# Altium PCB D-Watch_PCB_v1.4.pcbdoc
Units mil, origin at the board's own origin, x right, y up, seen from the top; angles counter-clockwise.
Board outline 2086.61 x 1990.87 mil, 4 copper layers (Top Layer, Inner1, Inner2, Bottom Layer); 71 components, 58 nets, 274 pads, 111 vias.
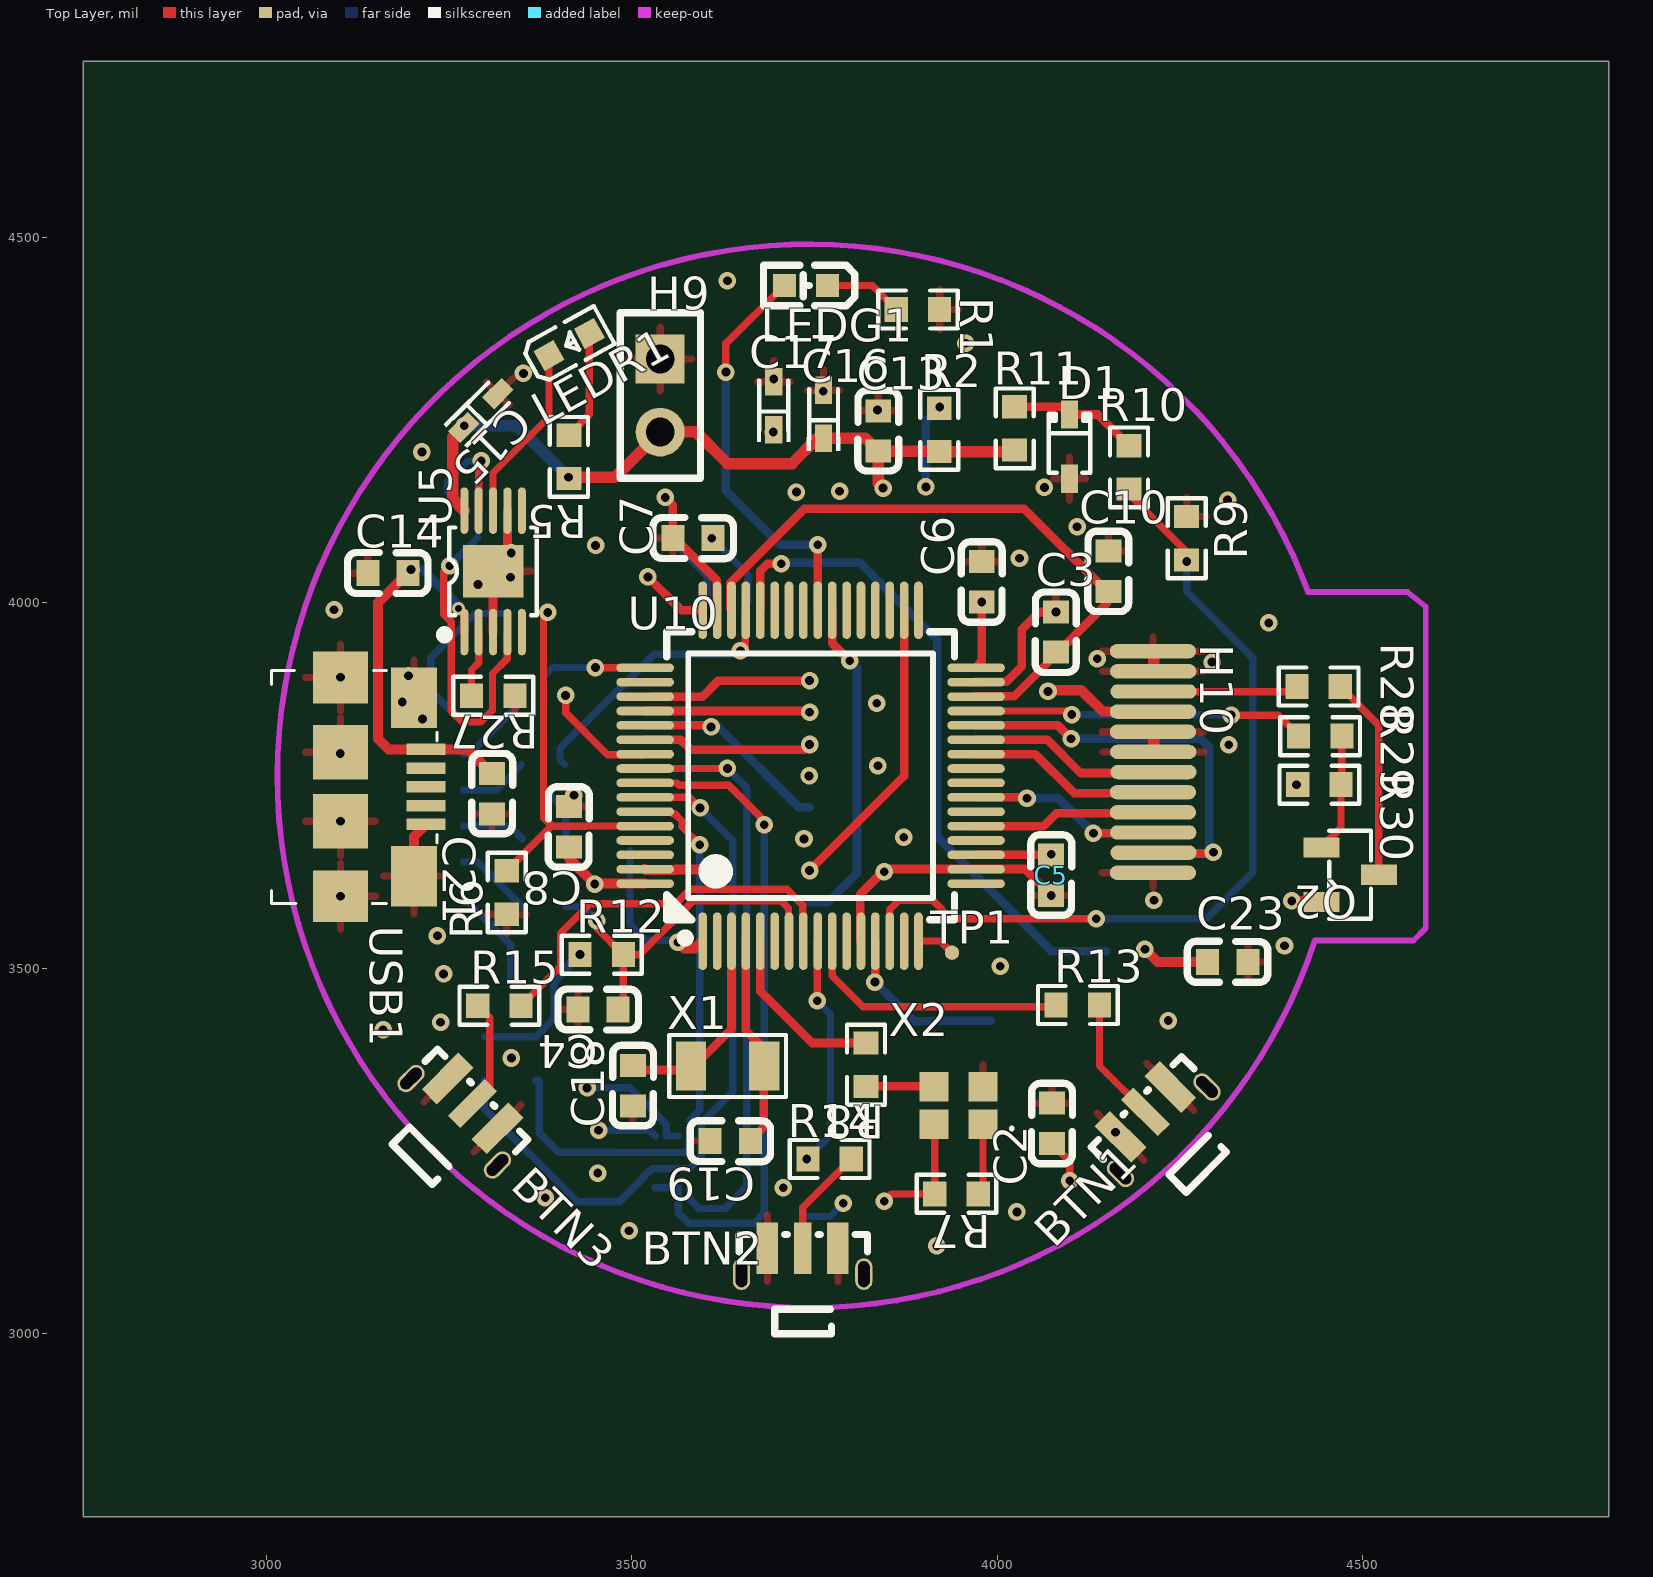
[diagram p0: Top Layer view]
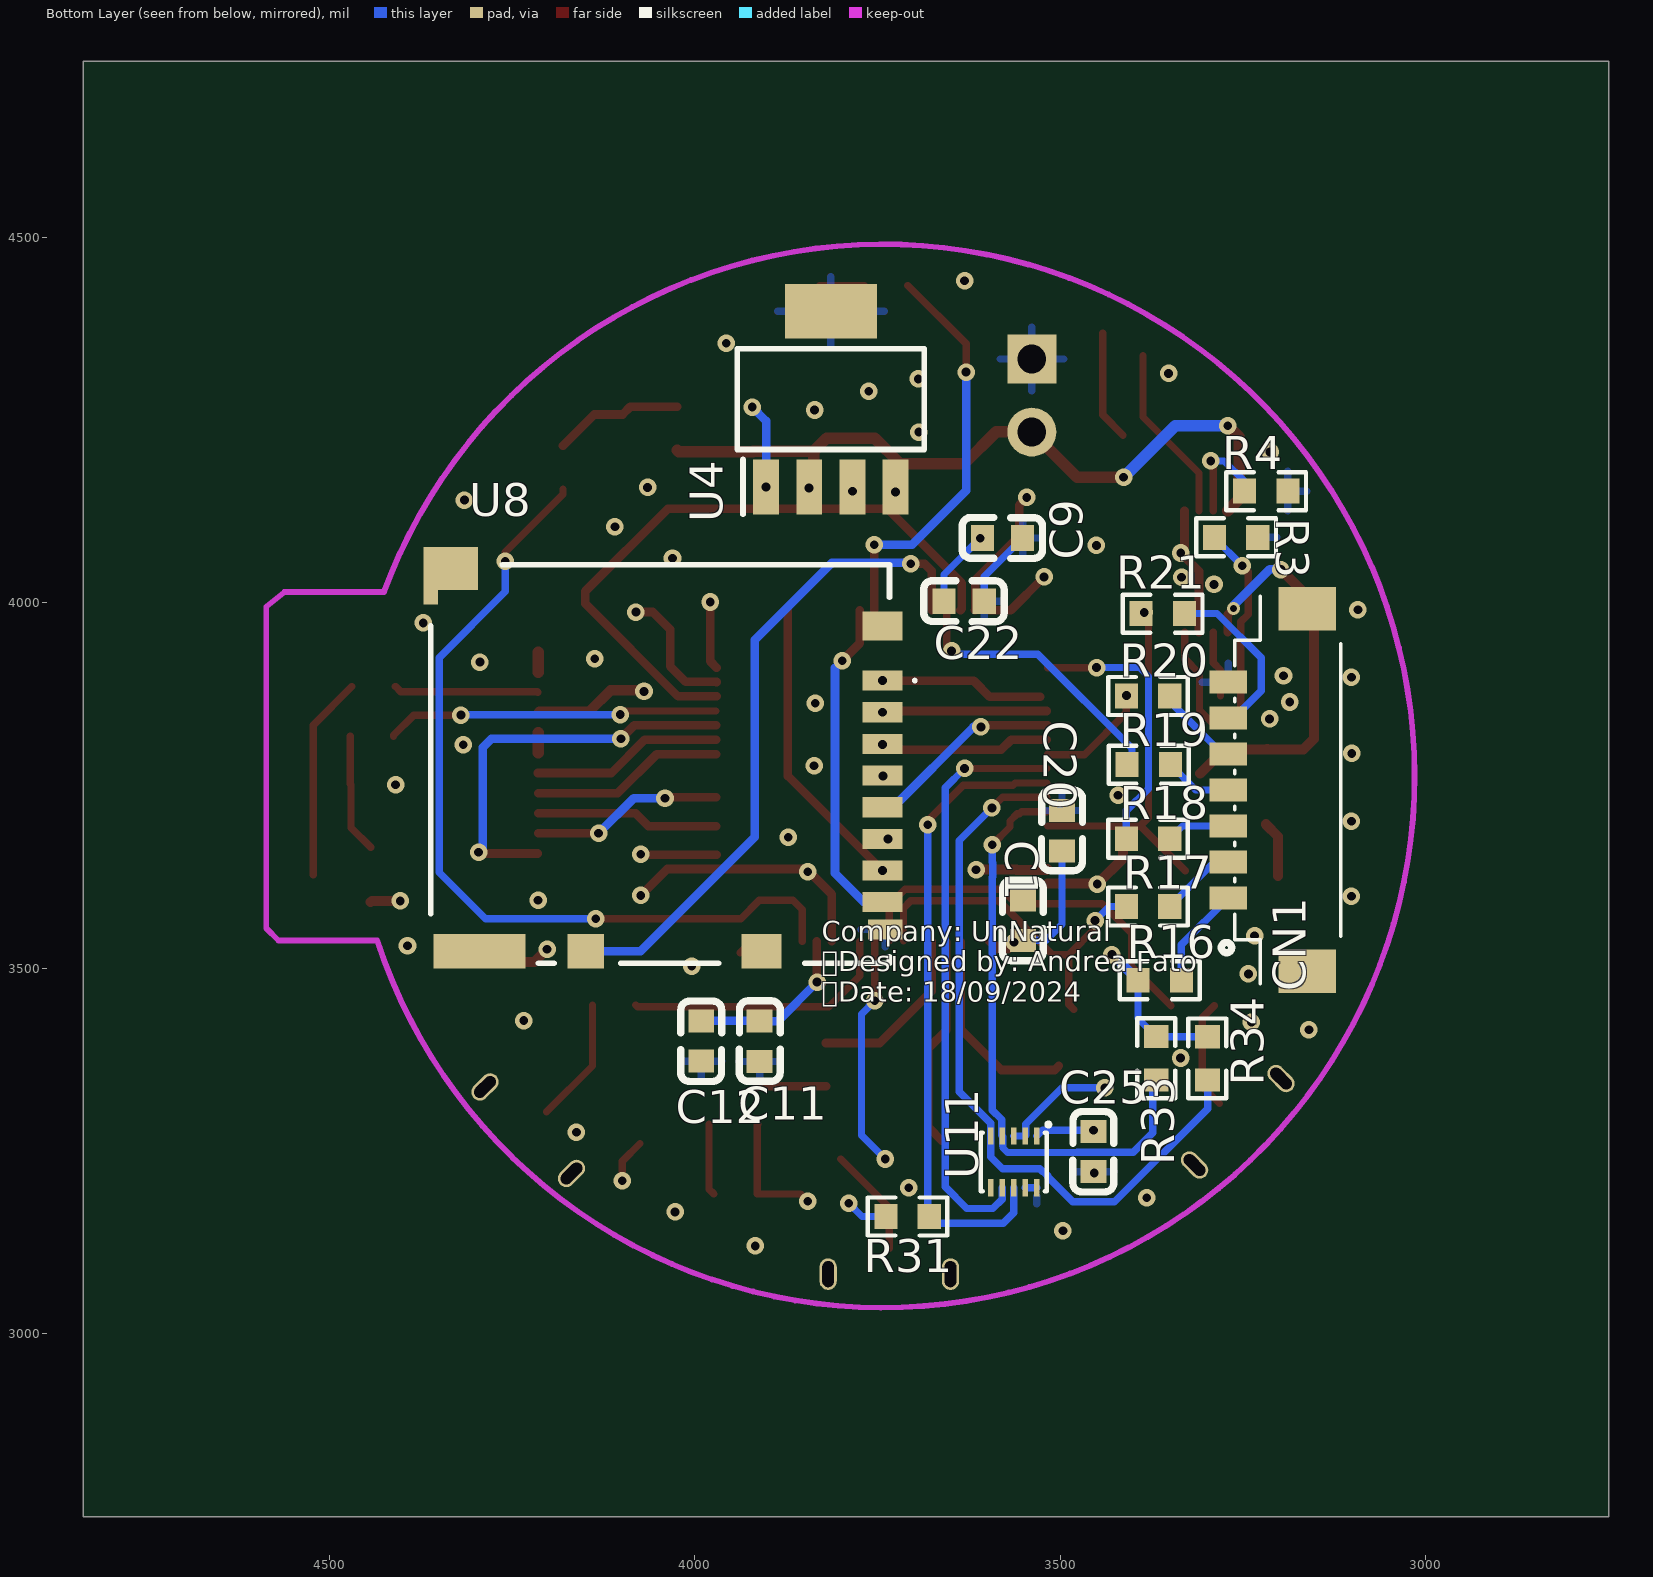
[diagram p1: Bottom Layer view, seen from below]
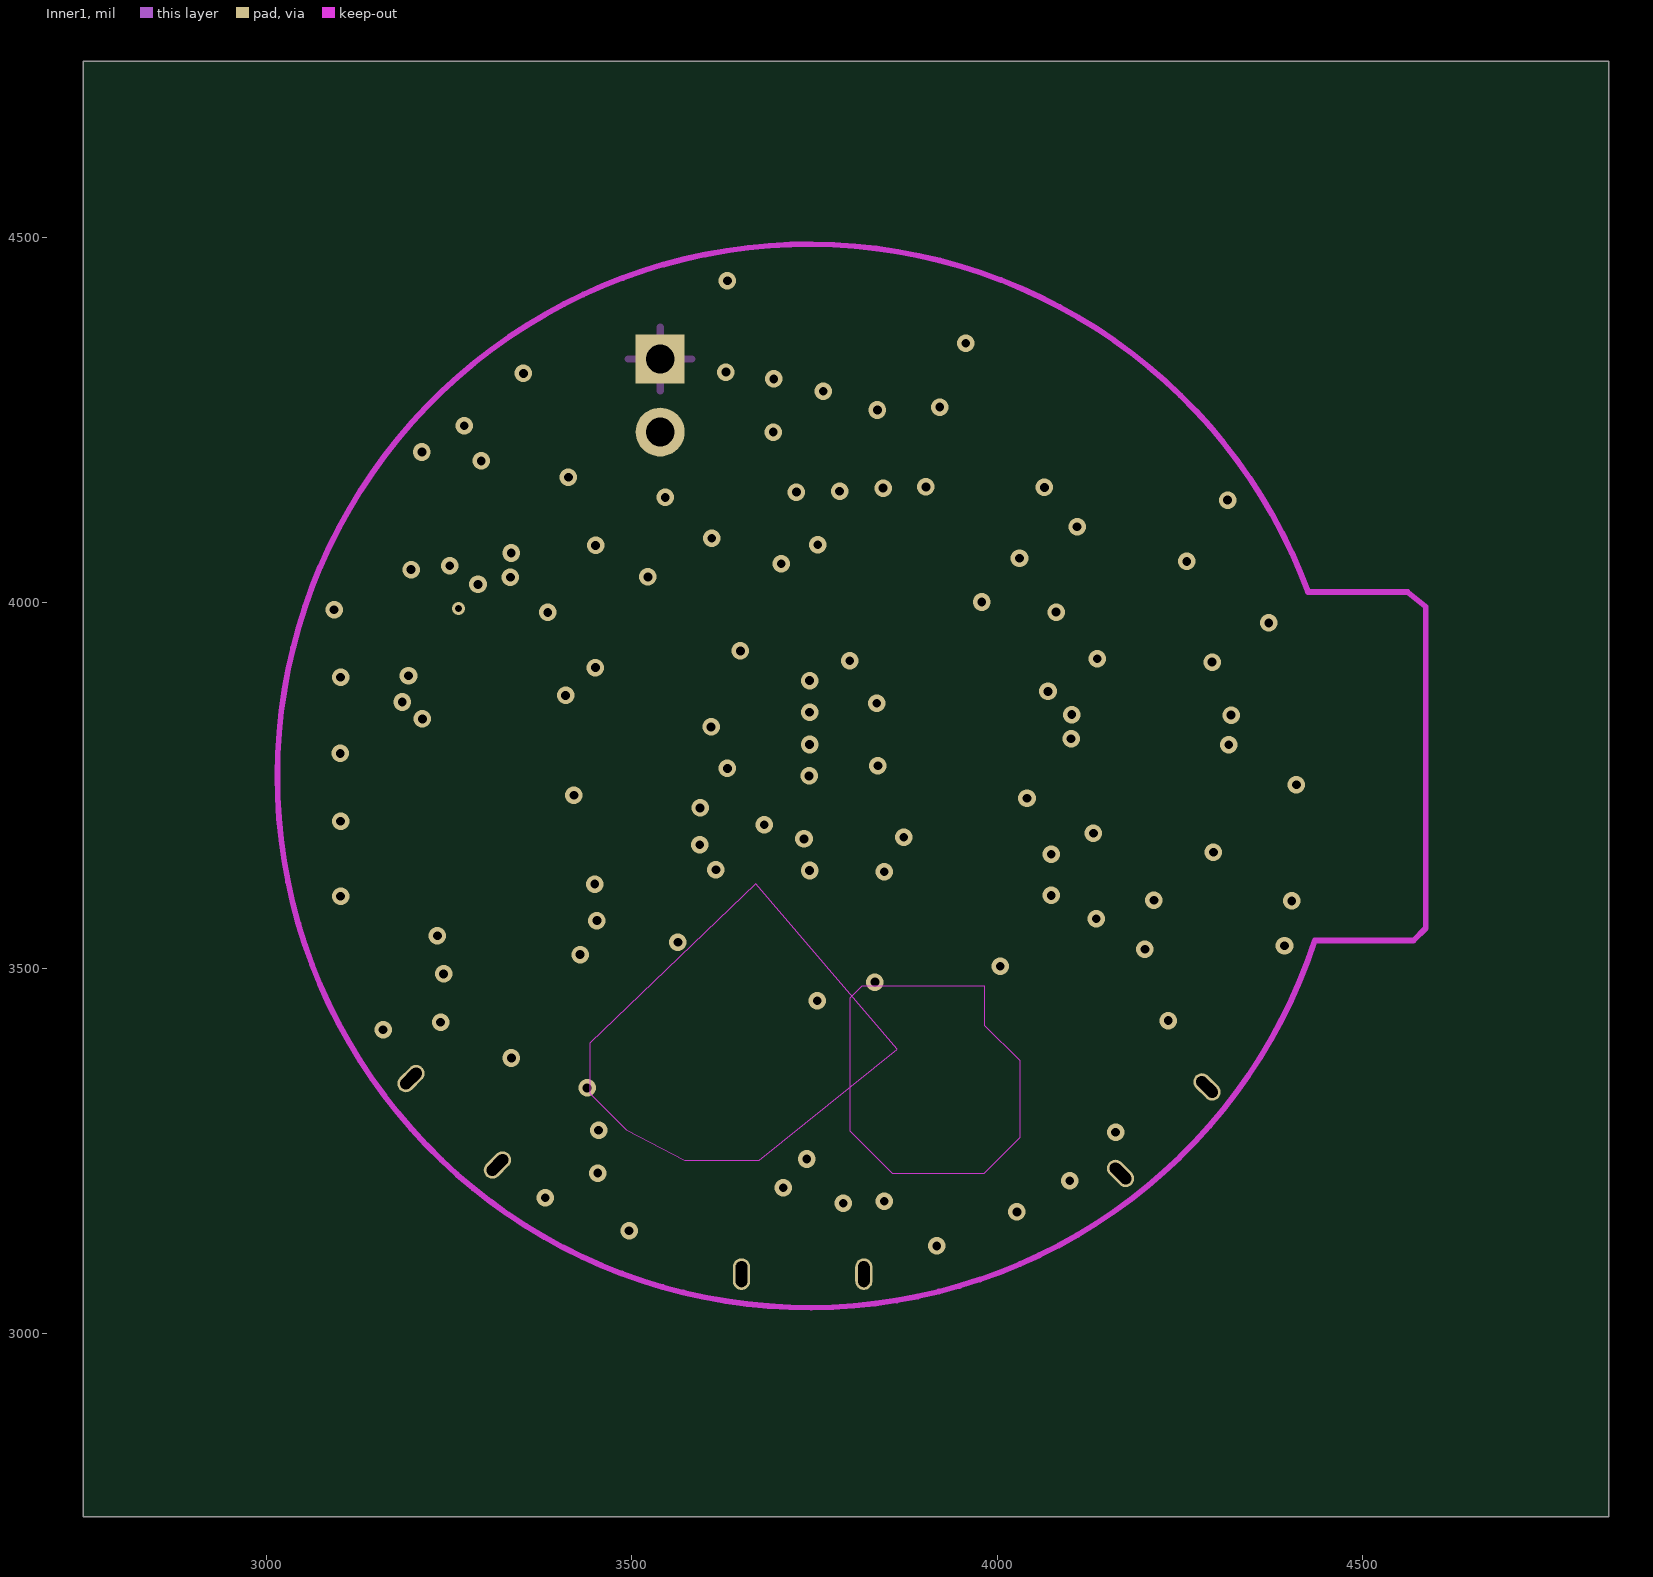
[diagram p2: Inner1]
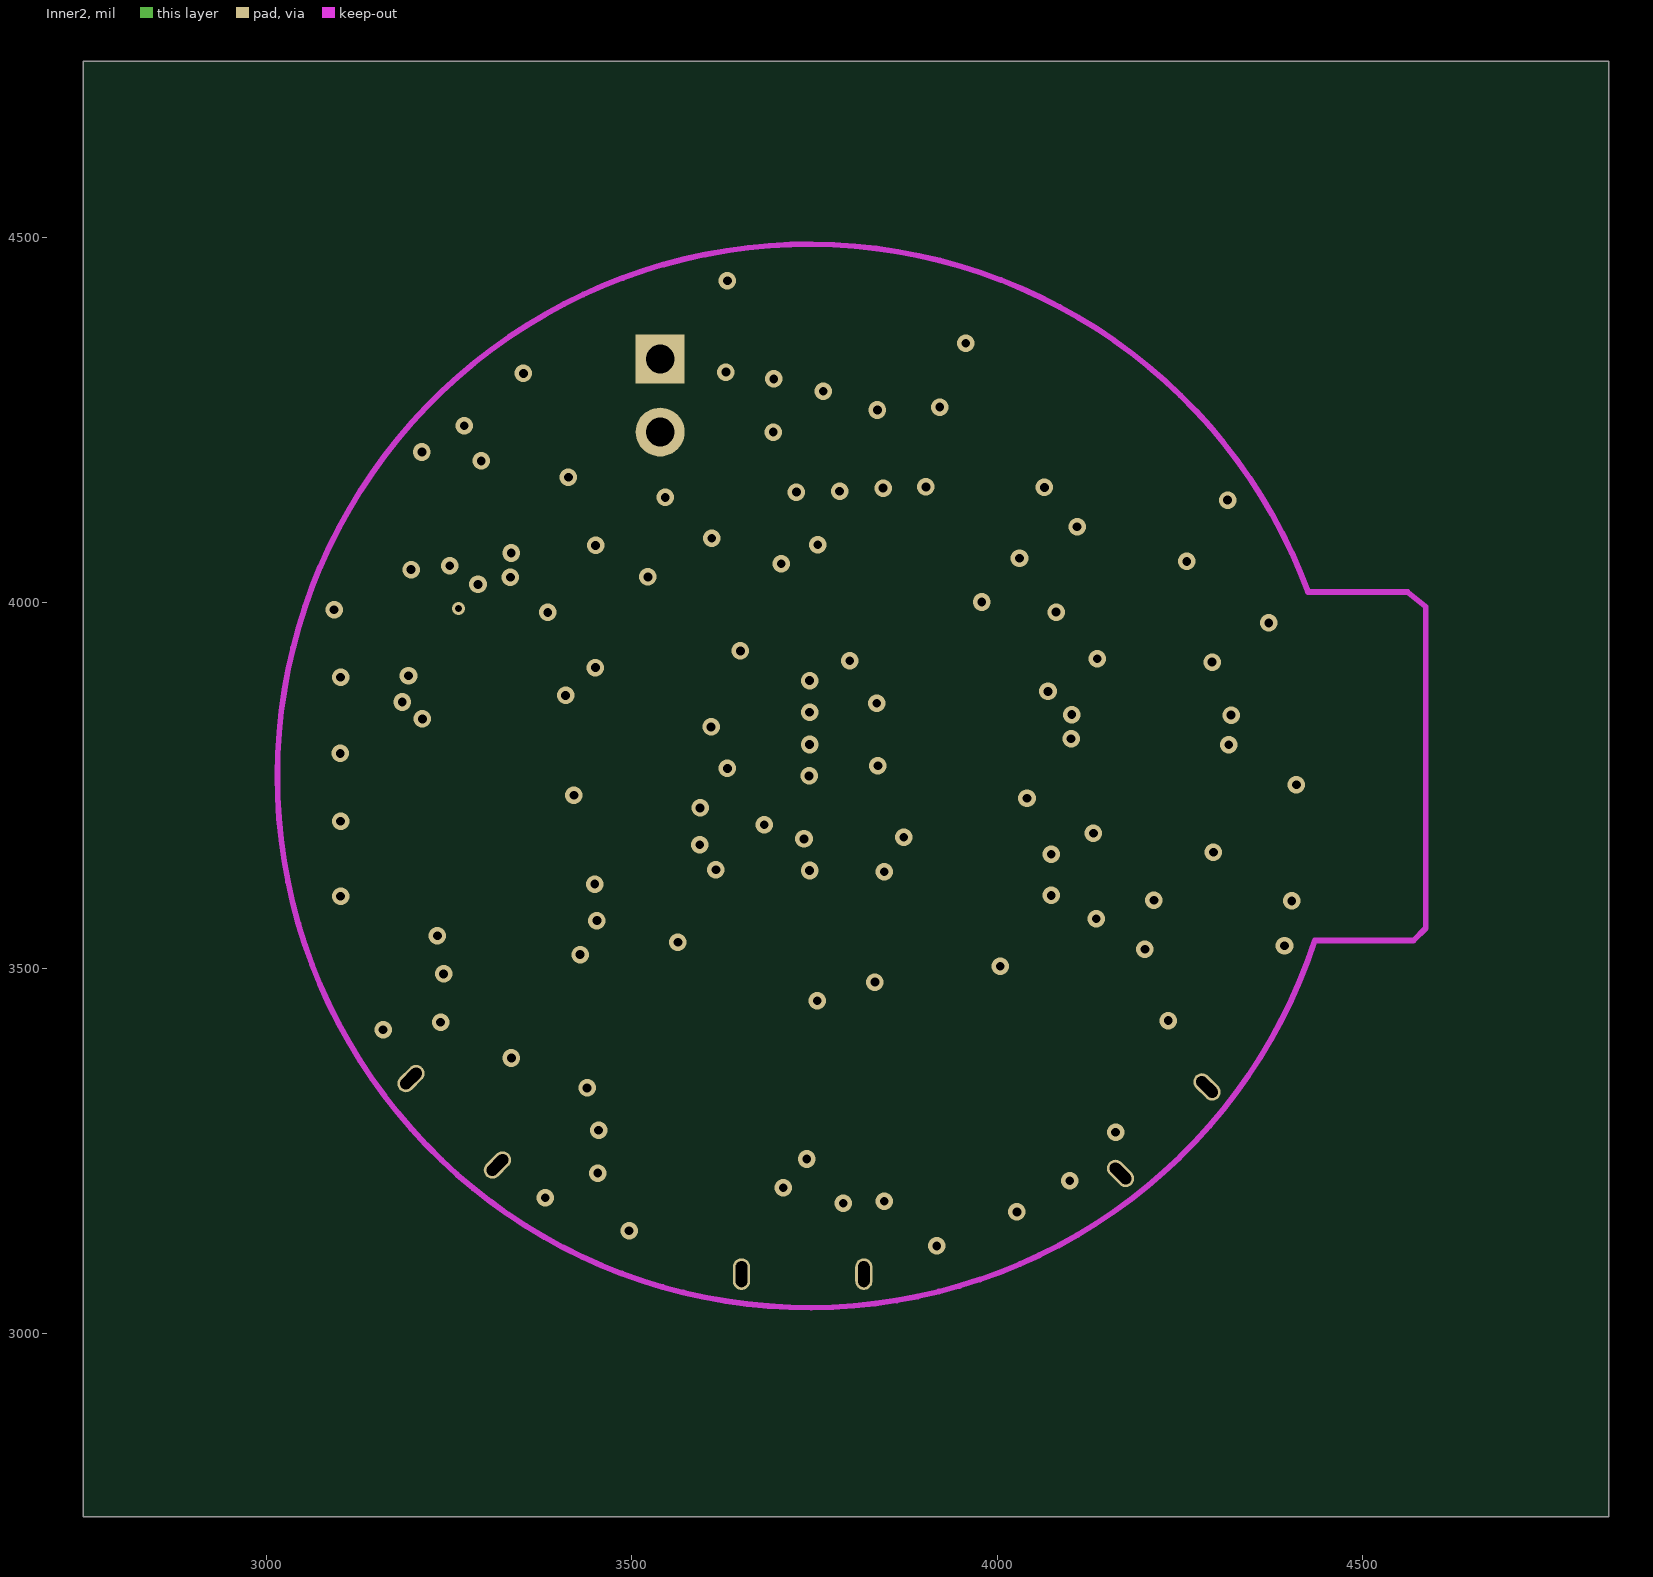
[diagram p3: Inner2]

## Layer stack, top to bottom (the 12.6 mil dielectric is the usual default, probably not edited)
Top Layer: signal copper (thickness not stored)
Dielectric: dielectric 12.6, FR-4, Dk 4.8
Inner1: signal copper (thickness not stored)
Dielectric: dielectric 12.6, FR-4, Dk 4.8
Inner2: signal copper (thickness not stored)
Dielectric: dielectric 12.6, FR-4, Dk 4.8
Bottom Layer: signal copper (thickness not stored)

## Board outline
4836.61,2750 2750,2750 2750,4740.87 4836.61,4740.87

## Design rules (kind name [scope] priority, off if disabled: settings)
Clearance copperThickness1oz [All] p1: gap=7 ignorepadtopadclearanceinfootprint=FALSE except(0.4: SMDPad-SMDPad; 4: Track-Track; 6: Track-SMDPad Track-THPad SMDPad-THPad THPad-THPad Track-Via SMDPad-Via THPad-Via Via-Via Track-Fill SMDPad-Fill THPad-Fill Via-Fill Fill-Fill SMDPad-Region THPad-Region Via-Region Fill-Region Region-Region Track-Poly SMDPad-Poly THPad-Poly Via-Poly Fill-Poly Poly-Poly Track-Text SMDPad-Text THPad-Text Via-Text Fill-Text Region-Text Poly-Text Text-Text; 6.9: Track-Hole SMDPad-Hole THPad-Hole Via-Hole Fill-Hole Region-Hole Poly-Hole Text-Hole Sheet-Hole; 11.8: Track-Region Region-Poly Track-Sheet SMDPad-Sheet THPad-Sheet Via-Sheet Fill-Sheet Region-Sheet Poly-Sheet Text-Sheet)
Clearance copperThickness2oz [All] p1: gap=7 ignorepadtopadclearanceinfootprint=FALSE except(6: Track-SMDPad SMDPad-SMDPad Track-THPad SMDPad-THPad THPad-THPad Track-Via SMDPad-Via THPad-Via Via-Via SMDPad-Fill THPad-Fill Via-Fill Fill-Fill Track-Region SMDPad-Region THPad-Region Via-Region Region-Region Track-Poly SMDPad-Poly THPad-Poly Via-Poly Fill-Poly Region-Poly Poly-Poly Track-Text SMDPad-Text THPad-Text Via-Text Fill-Text Region-Text Poly-Text Text-Text; 6.9: Track-Hole SMDPad-Hole THPad-Hole Via-Hole Fill-Hole Region-Hole Poly-Hole Text-Hole Sheet-Hole; 8: Track-Track; 11.8: Track-Fill Fill-Region Track-Sheet SMDPad-Sheet THPad-Sheet Via-Sheet Fill-Sheet Region-Sheet Poly-Sheet Text-Sheet)
Clearance BGA [All] p1: gap=7 ignorepadtopadclearanceinfootprint=FALSE except(3.9: Track-Track Track-SMDPad SMDPad-SMDPad Track-THPad SMDPad-THPad THPad-THPad Track-Via SMDPad-Via THPad-Via Via-Via Track-Fill SMDPad-Fill THPad-Fill Via-Fill Fill-Fill Track-Region SMDPad-Region THPad-Region Via-Region Fill-Region Region-Region Track-Poly SMDPad-Poly THPad-Poly Via-Poly Fill-Poly Region-Poly Poly-Poly Track-Hole SMDPad-Hole THPad-Hole Via-Hole Fill-Hole Region-Hole Poly-Hole Text-Hole Sheet-Hole; 6: Track-Text SMDPad-Text THPad-Text Via-Text Fill-Text Region-Text Poly-Text Text-Text; 11.8: Track-Sheet SMDPad-Sheet THPad-Sheet Via-Sheet Fill-Sheet Region-Sheet Poly-Sheet Text-Sheet)
DiffPairsRouting differentialPair [All] p1: maxuncoupledlength=10 maxlimit=5.9843 mostfreqgap=5.9843 toplayer_minwidth=5 toplayer_prefwidth=10 toplayer_maxwidth=100 bottomlayer_minwidth=5 bottomlayer_prefwidth=10 bottomlayer_maxwidth=100 midlayer1_minwidth=5 midlayer1_prefwidth=10 midlayer1_maxwidth=100 midlayer2_minwidth=5 midlayer2_prefwidth=10 midlayer2_maxwidth=100
PasteMaskExpansion pasteMaskExpansion [All] p1:
PlaneConnect innerPlane [All] p1: planeconnectstyle=Relief reliefexpansion=20 reliefentries=4 reliefconductorwidth=10 reliefairgap=10
PolygonConnect copperRegion [All] p1: connectstyle=Relief reliefentries=4 reliefconductorwidth=10 polygonreliefangle="90 Angle" airgapwidth=10
PolygonConnect copperRegionOSC [All] p1: connectstyle=Relief reliefentries=4 reliefconductorwidth=10 polygonreliefangle="90 Angle" airgapwidth=10
RoutingVias viaSize [All] p1: viastyle="Through Hole" holewidth=12.0078 minholewidth=5.9056 maxholewidth=248.0314 width=24.0158 minwidth=9.8426 maxwidth=393.7008
SolderMaskExpansion solderMaskExpansion [All] p1: useseparateexpansions=TRUE expansion=2.0079 expansionbottom=2.0079
Width copperThickness1oz [All] p1: maxlimit=100 minlimit=4 preferedwidth=10
Width copperThickness2oz [All] p1: maxlimit=100 minlimit=8 preferedwidth=10

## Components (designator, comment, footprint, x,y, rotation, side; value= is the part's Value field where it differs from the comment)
BTN1 "436333033816" SW-SMD_436333033816 4232.96,3273.74 r45 top
BTN2 "436333033816" SW-SMD_436333033816 3734.06,3074.8 r0 top
BTN3 "436333033816" SW-SMD_436333033816 3252.36,3285.27 r315 top
C1 "GCJ188R71C104KA01D" C0603 3551.18,3565.98 r90 bottom
C2 "GCJ188R71C104KA01D" C0603 4075.2,3288.03 r90 top
C3 "GCJ188R71C104KA01D" C0603 4080.44,3960.24 r90 top
C4 "GCJ188R71C104KA01D" C0603 3454.06,3443.86 r180 top
C5 "GCJ188R71C104KA01D" C0603 4074.02,3627.4 r270 top
C6 "GCJ188R71C104KA01D" C0603 3979.06,4028.86 r90 top
C7 "GCJ188R71C104KA01D" C0603 3584.06,4088.86 r180 top
C8 "GCJ188R71C104KA01D" C0603 3414.06,3693.86 r90 top
C9 "GCJ188C70J475KE02D" C0603 3579.06,4088.86 r180 bottom
C10 "GCJ188R71C104KA01D" C0603 4152.36,4043.54 r90 top
C11 "GCJ188R71C104KA01D" C0603 3911.42,3400.23 r270 bottom
C12 "CC0603KRX7R5BB105" C0603 3991.34,3400.62 r90 bottom
C13 "CC0603KRX7R5BB105" C0603 3837.4,4235.27 r270 top
C14 "CC0603KRX7R5BB105" C0603 3166.54,4040.78 r0 top
C15 "T58MM106M6R3C0300" CAP-SMD_L1.6-W0.8-RD 3293.7,4263.22 r225 top
C16 "T58MM106M6R3C0300" CAP-SMD_L1.6-W0.8-RD 3762.6,4258.1 r270 top
C17 "T58MM106M6R3C0300" CAP-SMD_L1.6-W0.8-RD 3694.49,4269.91 r270 top
C18 "CAP_0603" C0603 3501.72,3339.33 r270 top
C19 "CAP_0603" C0603 3634.79,3263.71 r180 top
C20 "AC0603KRX7R6BB105" C0603 3497.76,3688.5 r270 bottom
C21 "GCJ188R71C104KA01D" C0603 3309.06,3738.81 r270 top
C22 "GCJ188R71C104KA01D" C0603 3631.7,4002.32 r180 bottom
C23 "GCJ188R71C104KA01D" C0603 4315.71,3508.82 r0 top
C25 "AC0603KRX7R6BB105" C0603 3454.73,3249.44 r90 bottom
CN1 "53398-0771" CONN-SMD_7P-P1.25_53398-0771 3216.35,3744.04 r90 bottom
D1 "TDZ3V6J,115" SOD-323_L1.7-W1.3-LS2.5-RD-1 4099.06,4213.86 r270 top
H9 "HDR-F_2.54_1x2P" HDR-TH_2P-P2.54-V-F 3539.06,4283.86 r270 top
H10 "HDR-M_2.54_1x12P" HDR-TH_12P-P2.54-V-M 4210.96,3781.34 r270 top
LEDG1 "APT1608MGC" LED-SMD_L1.6-W0.8-RD 3738.4,4434.41 r180 top
LEDR1 "APT1608SURCK" LED0603-RD 3414.57,4353.77 r28.78 top
Q2 "NSS40200LT1G" SOT-23-3_L2.9-W1.3-P1.90-LS2.4-BR 4483.07,3628.18 r180 top
R1 "Res_0603" R0603 3891.72,4401.47 r180 top
R2 "Res_0603" R0603 3920.87,4236.84 r90 top
R3 "Res_0603" R0603 3259.46,4089.72 r0 bottom
R4 "Res_0603" R0603 3218.39,4153.03 r180 bottom
R5 "Res_0603" R0603 3414.22,4199.93 r90 top
R6 "Res_0603" R0603 3329.06,3603.86 r90 top
R7 "Res_0603" R0603 3944.49,3191.44 r180 top
R8 "Res_0603" R0603 3820.74,3368.21 r90 top
R9 "Res_0603" R0603 4259.4,4088.52 r90 top
R10 "Res_0603" R0603 4180.58,4185.49 r90 top
R11 "Res_0603" R0603 4024.06,4238.86 r270 top
R12 "Res_0603" R0603 3459.06,3518.86 r0 top
R13 "Res_0603" R0603 4110.47,3449.96 r180 top
R14 "Res_0603" R0603 3770.87,3239.21 r180 top
R15 "Res_0603" R0603 3319.06,3448.86 r0 top
R16 "Res_0603" R0603 3364.06,3483.86 r180 bottom
R17 "Res_0603" R0603 3380,3584.67 r180 bottom
R18 "Res_0603" R0603 3380,3677.37 r180 bottom
R19 "Res_0603" R0603 3379.06,3778.86 r180 bottom
R20 "Res_0603" R0603 3380,3872.77 r180 bottom
R21 "Res_0603" R0603 3360,3985.47 r180 bottom
R27 "Res_0603" R0603 3310.63,3873.06 r180 top
R28 "Res_0603" R0603 4439.96,3885.64 r180 top
R29 "Res_0603" R0603 4442.12,3817.78 r180 top
R30 "Res_0603" R0603 4440.94,3751.41 r0 top
R31 "Res_0603" R0603 3709.06,3160.47 r0 bottom
R33 "Res_0603" R0603 3368.9,3377 r90 bottom
R34 "Res_0603" R0603 3298.86,3376.88 r90 bottom
TP1 "Test-Point" Test-Point-0.5mm 3938.33,3521.56 r0 top
U4 "LP3874EMP-3.3_NOPB_" SOT150P700X180-5N 3814.06,4278.86 r90 bottom
U5 "BQ24092DGQR" MSOP-10_L3.0-W3.0-P0.50-LS5.0-BL-EP 3310.39,4043.27 r0 top
U8 "DM3BT-DSF-PEJS_" DM3BTDSFPEJS 4043.65,3788.45 r270 bottom
U10 "STM32H7B0RBT6" LQFP-64_L10.0-W10.0-P0.50-LS12.0-BL 3744.88,3763.62 r0 top
U11 "FXLS8964AFR3" DFN-10_L2.0-W2.0-P0.40-BL 3563.78,3235.27 r0 bottom
USB1 "10118192-0001LF" MICRO-USB-SMD_10118192-0001LF_1 3160.31,3748.38 r270 top
X1 "NX3215SA-32.768K-STD-MUA-9" CRYSTAL-SMD_L3.2-W1.5-1 3631.32,3366.42 r0 top
X2 "EC5625ETTTS-25.000M_TR_" EC5625ETTTS25000MTR 3947.25,3312.44 r180 top

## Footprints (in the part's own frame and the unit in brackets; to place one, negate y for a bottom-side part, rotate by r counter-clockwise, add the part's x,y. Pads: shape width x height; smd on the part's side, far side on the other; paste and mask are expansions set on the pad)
C0603 [mm]
  rect 0.8x0.9 smd: 1(-0.7,0) 2(0.7,0)
  silkscreen extent -1.41,-0.71 1.39,0.72
CAP-SMD_L1.6-W0.8-RD [mil]
  rect 37.57x23.39 smd: 1(32.86,0) 2(-32.86,0)
  silkscreen extent -34,-23 49,23
CONN-SMD_7P-P1.25_53398-0771 [mm]
  rect 0.8x1.3 smd: 1(-3.75,1.375) 2(-2.5,1.375) 3(-1.25,1.375) 4(0,1.375) 5(1.25,1.375) 6(2.5,1.375) 7(3.75,1.375)
  rect 1.5x2 smd: 8(6.3,-1.375) 9(-6.3,-1.375)
  silkscreen extent -6.73,-2.54 6.73,1.61
CRYSTAL-SMD_L3.2-W1.5-1 [mm]
  rect 1.05x1.7 smd: 1(-1.275,0) 2(1.275,0)
  silkscreen extent -2.03,-1.08 2.03,1.08
DFN-10_L2.0-W2.0-P0.40-BL [mm]
  rect 0.2x0.6 smd: 1(-0.8,-0.9) 2(-0.4,-0.9) 3(0,-0.9) 4(0.4,-0.9) 5(0.8,-0.9) 6(0.8,0.9) 7(0.4,0.9) 8(0,0.9) 9(-0.4,0.9) 10(-0.8,0.9)
  silkscreen extent -1.26,-1.36 1.14,1.02
DM3BTDSFPEJS [mm]
  rect 0.7x1.4 smd: 1(-2.675,7.625) 2(-1.575,7.625) 3(-0.475,7.625) 4(0.625,7.625) 5(1.725,7.625) 6(2.825,7.625) 7(3.925,7.625) 8(5.025,7.625)
  rect 1.2x1.27 smd: 9(6.725,-2.68)
  rect 0.7x1.2 smd: 10(5.975,7.725)
  rect 1x1.4 smd: 11(-4.575,7.625)
  rect 1.2x1.397 smd: 12(6.725,3.425)
  rect 1.2x3.2 smd: 13(6.725,-6.375)
  rect 1.5x1.9 smd: 14(-6.575,-7.375)
  rect 0.5x0.5 smd: 15(-5.575,-8.075)
  silkscreen extent -6.7,-8.07 7.15,8.8
EC5625ETTTS25000MTR [mm]
  rect 1x1.016 smd: 1(-0.85,0.65) 2(-0.85,-0.65) 3(0.85,-0.65) 4(0.85,0.65)
  silkscreen extent -1.9,0.75 -1.8,0.85
HDR-TH_2P-P2.54-V-F [mm]
  rect 1.7x1.7 hole 1: 1(-1.27,0)
  round 1.7 hole 1: 2(1.27,0)
  silkscreen extent -2.88,-1.39 2.88,1.4
HDR-TH_12P-P2.54-V-M [mm]
  oval 0.5x3 smd: 1(-3.877,0.059) 2(-3.177,0.069) 3(-2.477,0.079) 4(-1.777,0.059) 5(-1.077,0.059) 6(-0.377,0.069) 7(0.323,0.079) 8(1.023,0.059) 9(1.723,0.059) 10(2.423,0.069) 11(3.123,0.079) 12(3.823,0.059)
LED0603-RD [mm]
  rect 0.8x0.8 smd: 1(-0.799,0) 2(0.799,0)
  silkscreen extent -1.49,-0.75 1.39,0.76
LED-SMD_L1.6-W0.8-RD [mm]
  rect 0.8x0.8 smd: 1(-0.75,0) 2(0.75,0)
  silkscreen extent -1.7,-0.7 1.47,0.7
LQFP-64_L10.0-W10.0-P0.50-LS12.0-BL [mm]
  oval 0.3x2 smd: 1(-3.75,-5.75) 2(-3.25,-5.75) 3(-2.75,-5.75) 4(-2.25,-5.75) 5(-1.75,-5.75) 6(-1.25,-5.75) 7(-0.75,-5.75) 8(-0.25,-5.75) 9(0.25,-5.75) 10(0.75,-5.75) 11(1.25,-5.75) 12(1.75,-5.75) 13(2.25,-5.75) 14(2.75,-5.75) 15(3.25,-5.75) 16(3.75,-5.75) 33(3.75,5.75) 34(3.25,5.75) 35(2.75,5.75) 36(2.25,5.75) 37(1.75,5.75) 38(1.25,5.75) 39(0.75,5.75) 40(0.25,5.75) 41(-0.25,5.75) 42(-0.75,5.75) 43(-1.25,5.75) 44(-1.75,5.75) 45(-2.25,5.75) 46(-2.75,5.75) 47(-3.25,5.75) 48(-3.75,5.75)
  oval 2x0.3 smd: 17(5.75,-3.75) 18(5.75,-3.25) 19(5.75,-2.75) 20(5.75,-2.25) 21(5.75,-1.75) 22(5.75,-1.25) 23(5.75,-0.75) 24(5.75,-0.25) 25(5.75,0.25) 26(5.75,0.75) 27(5.75,1.25) 28(5.75,1.75) 29(5.75,2.25) 30(5.75,2.75) 31(5.75,3.25) 32(5.75,3.75) 49(-5.75,3.75) 50(-5.75,3.25) 51(-5.75,2.75) 52(-5.75,2.25) 53(-5.75,1.75) 54(-5.75,1.25) 55(-5.75,0.75) 56(-5.75,0.25) 57(-5.75,-0.25) 58(-5.75,-0.75) 59(-5.75,-1.25) 60(-5.75,-1.75) 61(-5.75,-2.25) 62(-5.75,-2.75) 63(-5.75,-3.25) 64(-5.75,-3.75)
  silkscreen extent -5,-5.79 5,5
MICRO-USB-SMD_10118192-0001LF_1 [mm]
  rect 0.4x1.35 smd: 1(-1.3,1.487) 2(-0.65,1.487) 3(0,1.487) 4(0.65,1.487) 5(1.3,1.487)
  rect 1.8x1.9 smd: 6(-3.8,-1.487) 6(3.8,-1.487)
  rect 2.1x1.6 smd: 6(-3.1,1.063) 6(3.1,1.063)
  rect 1.9x1.9 smd: 6(-1.199,-1.487) 6(1.199,-1.487)
  silkscreen extent -4.05,-3.89 4.05,1.86
MSOP-10_L3.0-W3.0-P0.50-LS5.0-BL-EP [mm]
  oval 0.28x1.62 smd: 1(-1,-2.11) 2(-0.5,-2.11) 3(0,-2.11) 4(0.5,-2.11) 5(1,-2.11) 6(1,2.11) 7(0.5,2.11) 8(0,2.11) 9(-0.5,2.11) 10(-1,2.11)
  rect 2.1x1.83 smd: 11(0,0)
  silkscreen extent -1.84,-2.35 1.52,1.52
R0603 [mil]
  rect 31.75x34.02 smd: 1(-29.66,0) 2(29.66,0)
  silkscreen extent -55,-26 55,26
SOD-323_L1.7-W1.3-LS2.5-RD-1 [mm]
  rect 0.985x0.6 smd: 1(-1.118,0) 2(1.118,0)
  silkscreen extent -1.15,-0.73 0.9,0.73
SOT150P700X180-5N [mm]
  rect 1.9x0.9 smd: 1(-3.05,2.25) 2(-3.05,0.75) 3(-3.05,-0.75) 4(-3.05,-2.25)
  rect 1.9x3.2 smd: 5(3.05,0)
  silkscreen extent -4,-3.25 1.75,3.25
SOT-23-3_L2.9-W1.3-P1.90-LS2.4-BR [mm]
  rect 1.25x0.7 smd: 1(1,-0.95) 2(1,0.95) 3(-1,0)
  silkscreen extent -0.73,-1.53 0.73,1.53
SW-SMD_436333033816 [mm]
  rect 0.75x1.8 smd: 1(-1.225,1.075) 3(1.225,1.075)
  rect 0.6x1.8 smd: 2(0,1.075)
  oval 0.6x1.1 hole 0.4 slot 0.9 at 90 deg: 6(-2.125,0.175) 6(2.125,0.175)
  silkscreen extent -2.2,-1.9 2.25,1.55
Test-Point-0.5mm [mm]
  round 0.5 smd: 1(0,0)

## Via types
v1: diameter 24.02, hole 12.01, Top Layer to Bottom Layer, 110 vias
v2: diameter 17.72, hole 9.84, Top Layer to Bottom Layer, 1 vias

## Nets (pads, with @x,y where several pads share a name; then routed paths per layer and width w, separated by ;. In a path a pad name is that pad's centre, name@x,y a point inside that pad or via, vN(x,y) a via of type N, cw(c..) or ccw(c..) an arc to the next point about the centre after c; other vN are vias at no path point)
5V_USB_CHGR: C14.2 C21.1 U5.1 USB1.1 | length 549.6
  Top Layer w11.81: v2(3262.9,3992.4) 3271.02,3984.29 U5.1
  Top Layer w13.78: v1(3198.28,4045.75) 3153.15,4000.62 3153.15,3814.01 3167.6,3799.56 3216.44,3799.56 USB1.1@3216.91,3800.04 ; USB1.1 3275.85,3799.58 C21.1
  Bottom Layer w11.81: v1(3198.28,4045.75) 3198.82,4046.29 3213.39,4046.29 3262.9,3996.78 v2(3262.9,3992.4)
$1N5489: R2.2 U4.1 | length 117.2
  Bottom Layer w11.81: v1(3902.64,4158.78) 3902.64,4249.07 v1(3921.65,4268.08)
$1N5967: R3.2 U5.4 | length 445.3
  Top Layer w10: v1(3251.06,4050.79) 3243.06,4042.79 3243.06,3984.18 3253.06,3974.18 3253.06,3852.56 3268.38,3837.24 3293.56,3837.24 3309.61,3853.29 3309.61,3903.54 3329.92,3923.85 3329.92,3960.04 U5.4
  Bottom Layer w10: v1(3251.06,4050.79) 3289.12,4088.84 R3.2
$1N5968: R27.2 U5.2 | length 91.2
  Top Layer w10: R27.2 3280.97,3908.37 3290.71,3918.1 U5.2
$1N5969: R4.1 U5.9 | length 140.7
  Top Layer w10: U5.9 3290.71,4190.66 v1(3294.37,4194.32)
  Bottom Layer w10: R4.1 3248.05,4166.39 3275.99,4194.32 v1(3294.37,4194.32)
$1N5973: LEDR1.1 U5.8 | length 244
  Top Layer w10: U5.8 3310.39,4177.83 3386.98,4254.42 LEDR1.1
$1N5974: LEDR1.2 R5.2 | length 150.9
  Top Layer w10: R5.2 3442.16,4257.53 LEDR1.2
$1N21382: LEDG1.1 R1.2 | length 107.8
  Top Layer w10: LEDG1.1 3829.13,4434.41 R1.2
$2N8217: R7.1 X2.1 | length 98.1
  Top Layer w10: R7.1 3980.71,3198 X2.1
$2N8264: R8.1 X2.3 | length 93.3
  Top Layer w11.81: R8.1 3913.26,3338.55 X2.3
$2N18890: D1.1 R10.2 R11.1 | length 178.6
  Top Layer w11.81: R11.1 4088.4,4268.52 D1.1 4137.87,4257.86 R10.2
$2N23973: TP1.1 U10.16 | length 53.2
  Top Layer w10: U10.16@3891.7,3537.49 3922.41,3537.49 TP1.1
$3N1058: CN1.1 R16.2 | length 139
  Bottom Layer w10: CN1.1 3334.4,3532.49 R16.2
$3N1061: CN1.2 R17.2 | length 105.1
  Bottom Layer w10: CN1.2 3289.39,3645.61 R17.2
$3N1065: CN1.3 R18.2 | length 87.1
  Bottom Layer w10: CN1.3 3332.87,3694.83 R18.2
$3N1094: CN1.4 R19.2 | length 93.3
  Bottom Layer w10: CN1.4 3314.59,3744.04 R19.2
$3N1097: CN1.5 R20.2 | length 117.1
  Bottom Layer w10: CN1.5 3278.14,3793.25 3350.34,3865.45 R20.2
$3N1126: CN1.6 R21.2 | length 236
  Bottom Layer w10: CN1.6 3262.83,3842.46 3225.2,3880.09 3225.2,3925.03 3285.64,3985.47 R21.2
$3N2256: BTN2.2 R14.1 | length 149.6
  Top Layer w10: BTN2.2 3734.06,3172.74 R14.1
$3N2358: BTN3.2 R15.1 | length 150.3
  Top Layer w10: BTN3.2 3305.91,3338.81 3305.91,3432.35 R15.1
$3N11256: BTN1.2 R13.1 | length 172.4
  Top Layer w10: R13.1 4140.13,3366.57 BTN1.2
$3N22100: H10.3 R28.2 | length 198.7
  Top Layer w10: H10.3@4214.92,3877.67 4215.71,3878.46 4402.34,3878.46 4409.52,3885.64 R28.2
$3N22908: Q2.1 R29.1 R30.2 | length 163.8
  Top Layer w10: Q2.1 4470.6,3692.49 R30.2 4471.78,3752.59 R29.1
$3N22933: Q2.3 R28.1 | length 279.3
  Top Layer w10: R28.1 4522.44,3832.82 Q2.3
+3V3: 
ADC1_IN16: R9.1 R10.1 U10.14 | length 1176.7
  Top Layer w10: U10.14 3853.15,3580.55 3865.75,3593.14 3911.81,3593.14 3937,3567.95 v1(4135.83,3567.95) ; R10.1 4180.58,4148.58 4259.4,4069.76 v1(4259.4,4056.89)
  Bottom Layer w10: v1(4135.83,3567.95) 4286.62,3567.95 4350,3631.33 4350,3925.03 4259.4,4015.63 v1(4259.4,4056.89)
BOOT0: R6.2 R21.1 U10.60 | length 513.3
  Top Layer w10: R6.2 3390.5,3694.96 ; v1(3385.2,3987.04) 3379.53,3981.38 3379.53,3705.93 3390.5,3694.96 ; U10.60@3517.69,3694.96 3436.6,3694.96 3436.33,3694.69 3391.8,3694.69 3391.52,3694.96 3390.5,3694.96
FXLS8974CF_INT: R31.1 U10.57 U11.8 | length 884.6
  Top Layer w10: U10.57 3561.76,3753.78 3564.96,3750.58 3633.04,3750.58 3681.42,3702.2 v1(3681.42,3696.69)
  Bottom Layer w10: U11.8 3563.79,3165.58 3577.95,3151.41 3667.32,3151.41 3681.42,3165.51 v1(3681.42,3696.69)
FXLS8974CF_WAKEUP: U10.56 U11.7 | length 807.1
  Top Layer w10: U10.56 3518.63,3773.58 v1(3631.1,3773.58)
  Bottom Layer w10: U11.7 3579.53,3184.3 3592.34,3171.49 3627.95,3171.49 3657.48,3201.02 3657.48,3747.19 v1(3631.1,3773.58)
GC9A01_BL: R29.2 U10.29 | length 456.1
  Top Layer w10: U10.29 4097.12,3852.2 v1(4102.11,3847.21) ; v1(4320.23,3846.55) 4384.78,3846.55 4412.46,3818.87 R29.2
  Bottom Layer w10: v1(4102.11,3847.21) 4319.56,3847.21 v1(4320.23,3846.55)
GC9A01_CS: H10.8 U10.26 | length 264.9
  Top Layer w11.81: U10.26 4052.36,3793.15 4105.63,3739.88 H10.8@4214.14,3739.88
GC9A01_DC: H10.7 U10.27 | length 262.5
  Top Layer w11.81: U10.27 4068.9,3812.83 4114.29,3767.43 H10.7@4214.92,3767.43
GC9A01_RST: H10.11 U10.28 | length 559.2
  Top Layer w11.81: U10.28 4083.01,3832.52 v1(4101.35,3814.18) ; H10.11@4214.92,3657.2 4294.45,3657.2 v1(4296.02,3658.77)
  Bottom Layer w11.81: v1(4101.35,3814.18) 4278.35,3814.18 4290.16,3802.36 4290.16,3664.64 v1(4296.02,3658.77)
GND: BTN1.1 BTN1.3 BTN2.1 BTN2.3 BTN3.1 BTN3.3 C1.2 C2.2 C3.2 C4.2 C5.2 C6.2 C7.2 C8.2 C9.2 C10.2 C11.2 C12.1 C13.1 C14.1 C15.2 C16.2 C17.2 C18.2 C19.2 C20.1 C21.2 C22.2 C23.2 C25.1 CN1.7 D1.2 H9.1 H10.1 H10.2 H10.5 H10.6 H10.12 R1.1 R3.1 R4.2 R6.1 R9.2 R27.1 U4.5 U5.3 U5.7 U5.11 U8.6 U8.10 U10.12 U10.18 U10.31 U10.47 U10.63 U11.2 U11.3 U11.9 U11.10 USB1.5 USB1.6 X2.2 | length 1408.8
  Top Layer w11.81: U5.3 U5.11 3330.08,4062.96 U5.7 ; v1(3545.87,4144.37) 3556.3,4133.94 3556.3,4091.17 3616.54,4030.94 3616.54,3990.38 U10.47 ; U10.12@3812.96,3537.49 3812.96,3601.38 3843.7,3632.12 v1(3845.67,3632.12) 3849.61,3636.06 3970.86,3636.06 U10.18 ; U10.31@3970.43,3891.81 3970.59,3891.96 4012.6,3891.96 4033.86,3913.22 4033.86,3963.62 4057.81,3987.57 v1(4080.82,3987.57) ; U10.18@3971.25,3635.91 4037.94,3635.91 v1(4074.02,3599.84)
  Top Layer w13.78: USB1.6@3202.16,3626.33 3202.16,3680.47 USB1.5 ; U10.63@3517.69,3635.91 3518.84,3634.76 3559.76,3634.76 3560.03,3635.03 v1(3615.36,3635.03)
  Top Layer w15.75: H10.5@4214.14,3822.55 4214.14,3795.39 H10.6@4214.53,3794.99 ; H10.1@4214.14,3932.79 4214.53,3932.4 H10.2@4214.53,3905.23
  Bottom Layer w10: v1(3438.97,3336.53) 3497.75,3336.53 3547.21,3287.07 3547.21,3271.53 U11.2 U11.3 ; U11.10 U11.9 ; C9.2 3604.14,4036.22 C22.2
  other v1: 3917.32,3120.31 3496.46,3141.18 3381.89,3186.06 3707.49,3199.87 3453.55,3219.92 4162.21,3275.82 3335.52,3377.4 3159.85,3415.98 3238.59,3426.22 4234.25,3428.58 3242.64,3492.51 4004.33,3502.99 4393.31,3530.94 3234.2,3544.71 4214.57,3593.14 3101.76,3598.78 3735.82,3677.23 3872.44,3679.36 3101.76,3701.18 3420.96,3736.98 3837.01,3777.4 3101.43,3794.18 4316.93,3806.14 3213.76,3841.37 3835.43,3862.83 3186.06,3864.53 3101.8,3898.43 3194.68,3900.35 4294.17,3919.13 4137.14,3923.62 4371.89,3972.67 3092.92,3990.78 3289.77,4025.43 3334.17,4035.24 4030.71,4061.25 3335.44,4068.34 3450.65,4078.68 4109.45,4104.17 4315.35,4140.78 4064.72,4158.03 3212.99,4206.53 3836.22,4264.01 3762.21,4289.78 3694.49,4306.53 3351.97,4314.01 3957.09,4355.35 3631.1,4440.78
I2C_SCL: R34.1 U10.58 U11.5 | length 1010.1
  Top Layer w10: U10.58 3579.14,3734.09 v1(3593.7,3719.52)
  Bottom Layer w10: R34.1 3298.86,3346.04 3298.47,3345.65 3298.47,3308.06 3425.99,3180.55 3482.9,3180.55 3517.37,3215.02 3517.37,3216.2 3523.8,3222.63 3524.98,3222.63 3528.17,3225.82 3579.14,3225.82 3595.24,3241.92 U11.5@3595.24,3269.48 ; v1(3593.7,3719.52) 3638.35,3674.87 3638.35,3331.35 3595.28,3288.28 U11.5 U11.5@3595.28,3269.53
I2C_SDA: R33.1 U10.59 U11.4 | length 813.4
  Top Layer w10: U10.59 3552.99,3714.41 3555.79,3711.61 3558.97,3711.61 3568.87,3701.71 3568.87,3693.41 v1(3593.15,3669.13)
  Bottom Layer w9.84: R33.1@3368.51,3346.16 3373.23,3346.16 3373.62,3345.77 3373.62,3275.03 3400.12,3248.54 3476.96,3248.54 3477.51,3247.99 3572.24,3247.99 3578.63,3254.38 3578.63,3256.89 3578.71,3256.97 U11.4@3578.71,3269.89
  Bottom Layer w10: U11.4 3580.36,3271.53 3580.36,3293.18 3593.15,3305.98 3593.15,3624.72 3592.36,3625.51 3592.36,3644.56 3593.15,3645.34 v1(3593.15,3669.13)
MINUS_BTN: R13.2 U10.10 | length 373.1
  Top Layer w10: U10.10@3773.59,3537.49 3774.43,3536.65 3774.43,3489.59 3816.54,3447.47 4078.32,3447.47 R13.2
OSC32_IN: C18.1 U10.3 X1.1 | length 279.9
  Top Layer w11.81: C18.1@3501.97,3366.77 3507.81,3360.93 3580.53,3360.93 3636.62,3417.02 U10.3@3636.62,3536.66
OSC32_OUT: C19.1 U10.4 X1.2 | length 291.8
  Top Layer w11.81: U10.4@3656.3,3536.67 3656.3,3415.19 3680.92,3390.57 3680.92,3283.08 C19.1@3661.11,3263.27
OSC_25M: R8.2 U10.5 | length 242.4
  Top Layer w11.81: U10.5 3675.98,3469.13 3747.25,3397.87 R8.2
PLUS_BTN: R15.2 U10.8 | length 535.9
  Top Layer w10: R15.2 3402.54,3502.68 3402.54,3547.86 3443.05,3588.37 3560.44,3588.37 3580.18,3608.1 3712.6,3608.1 3734.22,3586.48 U10.8@3734.22,3537.49
PWR_STAT: LEDG1.2 U10.40 | length 560
  Top Layer w10: v1(3628.95,4315.91) 3628.95,4354.49 LEDG1.2
  Top Layer w11.81: U10.40 v1(3754.73,4079.64)
  Bottom Layer w11.81: v1(3628.95,4315.91) 3628.95,4153.57 3702.88,4079.64 v1(3754.73,4079.64)
RESET#: C4.1 R12.2 R17.1 U10.7 | length 495.7
  Top Layer w10: v1(3452.57,3565.37) 3452.57,3555.01 R12.2 ; C4.1 3488.72,3450.96 R12.2 ; U10.7@3714.53,3537.49 3714.53,3582.39 3704.53,3592.39 3584.29,3592.39 3510.76,3518.86 R12.2
  Bottom Layer w10: R17.1 3433.28,3584.67 v1(3452.57,3565.37)
SDIO1_CLK: U8.5 U10.53 | length 272.2
  Top Layer w11.81: U10.53@3517.69,3832.76 3606.32,3832.76 v1(3608.73,3830.35)
  Bottom Layer w11.81: v1(3608.73,3830.35) 3618.8,3830.35 3728.61,3720.54 U8.5
SDIO1_CMD: U8.3 U10.54 | length 233.7
  Top Layer w11.81: U10.54 3567.36,3812.8 3581.1,3799.05 3736.24,3799.05 v1(3743.54,3806.35)
SDIO1_D0: U8.7 U10.34 | length 409.7
  Top Layer w11.81: v1(3743.46,3633.92) 3872.83,3763.3 U10.34
SDIO1_D1: U8.8 U10.39 | length 455
  Top Layer w11.81: U10.39 3774.41,3944.97 v1(3798.46,3920.91)
  Bottom Layer w11.81: U8.8 3768.73,3590.62 3808.27,3630.15 3808.27,3911.11 v1(3798.46,3920.91)
SDIO1_D2: U8.1 U10.51 | length 225.3
  Top Layer w11.81: U10.51@3527.44,3871.82 3527.78,3871.49 3596.46,3871.49 3618.65,3893.69 v1@3743.46,3893.69
  other v1: 3743.46,3893.77
SDIO1_D3: U8.2 U10.52 | length 225.7
  Top Layer w10: v1@3741.72,3852.2 v1(3743.46,3850.46)
  Top Layer w11.81: U10.52 v1@3741.72,3852.2
SET_BTN: R14.2 U10.9 | length 319.3
  Top Layer w10: v1(3753.9,3455.59) U10.9@3753.9,3537.49
  Bottom Layer w10: v1(3739.57,3239.21) 3772.05,3271.69 3772.05,3437.44 v1(3753.9,3455.59)
SPI1_MOSI: H10.10 U10.23 | length 263.7
  Top Layer w11.81: U10.23 4039.77,3734.09 v1(4040.95,3732.91) ; v1(4131.89,3684.88) 4214.41,3684.88 H10.10@4214.53,3684.76
  Bottom Layer w11.81: v1(4040.95,3732.91) 4083.86,3732.91 v1(4131.89,3684.88)
SPI1_SCK: H10.9 U10.21 | length 250.2
  Top Layer w11.81: U10.21 4063.78,3694.72 4081.38,3712.32 H10.9@4214.14,3712.32
TCK/SWCLK: R18.1 U10.49 | length 377.8
  Top Layer w10: v1(3450.4,3911.65) 3450.54,3911.5 U10.49@3517.69,3911.5
  Bottom Layer w10: R18.1 3409.66,3715.77 3379.53,3745.9 3379.53,3899.44 3391.73,3911.65 v1(3450.4,3911.65)
TDO/SWO: R20.1 U10.55 | length 156.1
  Top Layer w10: v1(3409.67,3873.56) 3409.67,3849.62 3466.93,3792.36 3516.66,3792.36 U10.55@3517.69,3793.39
TMS/SWDIO: R19.1 U10.45 | length 385.7
  Top Layer w10: v1(3648.87,3934.32) 3655.48,3940.94 U10.45@3655.48,3990.23
  Bottom Layer w10: R19.1 3402.03,3785.55 3402.03,3801.08 3530.95,3929.99 3644.54,3929.99 v1(3648.87,3934.32)
USD_DETECT: U8.9 U10.44 | length 909.7
  Top Layer w11.81: U10.44 3675.98,4043.79 3685.97,4053.77 v1(3704.86,4053.77)
  Bottom Layer w11.81: v1(3704.86,4053.77) 3706.04,4054.95 3812.6,4054.95 3918.11,3949.44 3918.11,3679.74 4074.17,3523.69 U8.9
VBAT: C13.2 C15.1 C16.1 H9.2 R2.1 R5.1 R11.2 U4.2 U5.10 | length 1031.3
  Top Layer w15.75: v1(3270.86,4242.46) 3255.12,4226.71 3255.12,4142.24 U5.10 ; v1(3413.43,4171.98) 3477.18,4171.98 H9.2 3539.5,4234.3 3587.59,4234.3 3631.1,4190.78 3719.48,4190.78 3753.94,4225.24 C16.1 3819.87,4225.24 C13.2 ; v1(3843.98,4157.2) 3837.4,4163.78 C13.2 ; R11.2 4022.05,4207.18 R2.1 3920.34,4207.71 C13.2
  Bottom Layer w15.75: v1(3270.86,4242.46) 3342.95,4242.46 v1(3413.43,4171.98)
VCAP: C3.1 C10.1 U10.30 U10.46 | length 891.3
  Top Layer w11.81: U10.46 3634.73,3991.87 3634.73,4027.15 3736.56,4128.98 4037,4128.98 4150.07,4015.91 4150.07,3999.11 4023.08,3872.13 U10.30@3970.43,3872.13
pads on no net: BTN1.6 BTN2.6 BTN3.6 C1.1 C2.1 C5.1 C6.1 C7.1 C8.1 C9.1 C11.1 C12.2 C17.1 C20.2 C22.1 C23.1 C25.2 CN1.8 CN1.9 H10.4 Q2.2 R7.2 R12.1 R16.1 R30.1 R31.2 R33.2 R34.2 U4.3 U4.4 U5.5 U5.6 U8.4 U8.11 U8.12 U8.13 U8.14 U8.15 U10.1 U10.2 U10.6 U10.11 U10.13 U10.15 U10.17 U10.19 U10.20 U10.22 U10.24 U10.25 U10.32 U10.33 U10.35 U10.36 U10.37 U10.38 U10.41 U10.42 U10.43 U10.48 U10.50 U10.61 U10.62 U10.64 U11.1 U11.6 USB1.2 USB1.3 USB1.4 X2.4
copper on no net: | length 1841.9
  Top Layer w10: v1(3845.67,3181.33) 3855.78,3191.44 3914.83,3191.44 3914.83,3285.8 3913.78,3286.85 ; 4075.2,3260.47 4099.53,3236.13 v1(4099.53,3209.41)
  Top Layer w11.81: v1(3522.28,4035.66) 3567.96,3989.99 3597.24,3989.99 ; v1(3832.92,3481.26) 3833.46,3481.81 3833.46,3537.25 ; 3970.43,3655.59 4073.51,3655.59 v1(4074.06,3656.14) ; 3970.43,3911.5 3979.06,3920.13 v1(3979.06,4001.3)
  Top Layer w13.78: 3414.06,3666.3 3414.06,3650.83 v1(3449.46,3615.43) 3450.24,3616.22 3517.69,3616.22 ; v1(3563.35,3535.9) 3571.86,3527.4 3586.33,3527.4 3596.42,3537.49 ; v1(4069.69,3878.97) 4071.26,3880.54 4115.36,3880.54 4144.21,3851.69 4212.56,3851.69 4214.13,3850.11 ; v1(4202.36,3526.21) 4219.76,3508.82 4288.15,3508.82 ; v1(4403.15,3592.36) 4442.13,3592.36 4443.7,3590.78
  Bottom Layer w10: 3298.86,3406.54 3368.78,3406.54 3368.9,3406.66 3393.72,3431.48 3393.72,3483.86 ; v1(3454.73,3278.58) 3524.41,3278.58 3532.29,3270.71 ; 3497.76,3660.94 3497.76,3560.35 3519.69,3538.42 3551.18,3538.42 ; v1(3609.65,4088.64) 3659.26,4039.03 3659.26,4002.32 ; 3738.72,3160.47 3771.36,3160.47 v1(3789.47,3178.58)
  Bottom Layer w11.81: v1(3832.92,3481.26) 3886.39,3427.79 3911.42,3427.79 3911.81,3428.18 3991.34,3428.18
  Bottom Layer w13.78: 3393.72,3483.86 3428.72,3518.86 v1(3429.4,3518.86)
  other v1: 4027.17,3166.77 4409.65,3751.41 3742.87,3763.34 3725.48,4151.69 3784.53,4152.87 3693.87,4233.83

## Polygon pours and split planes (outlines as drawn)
GND on Inner1 (solid, remove dead copper): 4452.56,3763.84 ccw(c3743.46,3762.04) 3034.36,3763.84 ccw(c3743.46,3765.65)
no net on Inner2 (solid, remove dead copper): 4464.58,3757.68 ccw(c3755.48,3756.1) 3046.38,3757.68 ccw(c3755.48,3759.25)
GND on Bottom Layer (solid, remove dead copper, pour order 2): 4452.34,3763.05 ccw(c3741.89,3761.78) 3031.43,3763.06 ccw(c3741.89,3764.34)
GND on Top Layer (solid, remove dead copper): 4449.23,3760.71 ccw(c3740.12,3760.71) 3031.02,3760.71 ccw(c3740.12,3760.71)

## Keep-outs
Inner1:
  region: 3670.12,3615.54 3442.64,3397.89 3442.64,3329.11 3492.78,3278.97 3572.82,3237.24 3674.77,3237.24 3863.42,3389.58
  region: 3798.43,3459.06 3798.43,3278.18 3856.69,3219.92 3982.68,3219.92 4031.89,3269.13 4031.89,3373.4 3983.47,3421.82 3983.47,3475.82 3815.18,3475.82
Board Outline Layer:
  lines w7.87: 4425.53,4014.9 ccw(c3742.87,3763.34) 4434.71,3538.25 4569.91,3538.25 4586.61,3554.95 4586.61,3994.95 4561.85,4014.9 4425.53,4014.9

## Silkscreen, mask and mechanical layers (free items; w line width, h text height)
Bottom Silkscreen Layer:
  text "Company: UnNatural /  Designed by: Andrea Fato /  Date: 18/09/2024" at 3826.77,3454.56 h27.56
